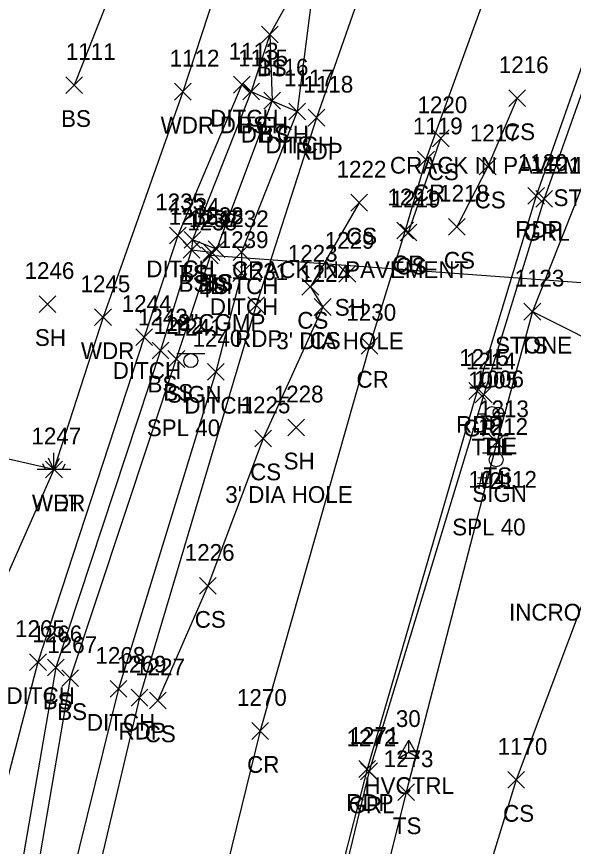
# Model space of a CAD drawing. Extents: x 1551995 to 1555700, y 777276 to 783130.
# Drawn here: x 1554895.2 to 1554961.7, y 778019 to 778118.1 of the extents above; entities that cross this region are included whole.
import ezdxf

# ---------------------------------------------------------------- set-up
doc = ezdxf.new("R2010")
doc.units = 0
for name, color, linetype in [('C_A', 7, 'Continuous'), ('C_C', 7, 'Continuous'), ('C_I', 7, 'Continuous'), ('CBP', 7, 'Continuous'), ('CPSM', 7, 'Continuous'), ('D_A', 7, 'Continuous'), ('D_C', 7, 'Continuous'), ('D_I', 7, 'Continuous'), ('D_TIC', 7, 'Continuous'), ('DCP', 7, 'Continuous'), ('DD', 7, 'Continuous'), ('L_A', 7, 'Continuous'), ('L_C', 7, 'Continuous'), ('L_I', 7, 'Continuous'), ('L_TIC', 7, 'Continuous'), ('LASF', 7, 'Continuous'), ('LAWA', 7, 'Continuous'), ('LELB', 7, 'Continuous'), ('LWET', 7, 'Continuous'), ('P_A', 7, 'Continuous'), ('P_I', 7, 'Continuous'), ('P_TIC', 7, 'Continuous'), ('PET', 7, 'Continuous'), ('PRC', 7, 'Continuous'), ('R_A', 7, 'Continuous'), ('R_I', 7, 'Continuous'), ('R_TIC', 7, 'Continuous'), ('RGR', 7, 'Continuous'), ('S_A', 7, 'Continuous'), ('S_C', 7, 'Continuous'), ('S_I', 7, 'Continuous'), ('SSGN', 7, 'Continuous'), ('U_A', 7, 'Continuous'), ('U_C', 7, 'Continuous'), ('U_I', 7, 'Continuous'), ('UP', 7, 'Continuous')]:
    doc.layers.add(name, color=color, linetype=linetype)

msp = doc.modelspace()

# ---------------------------------------------------------------- linework, layer by layer
at = {"layer": 'CBP'}
for radius in [0.625, 0.0833]:
    msp.add_circle((1554952.736, 778070.817), radius, dxfattribs=at)
at = {"layer": 'CPSM'}
for p, q in [((1554940.771, 778029.523), (1554942.021, 778031.688)), ((1554943.271, 778029.523), (1554942.021, 778031.688)), ((1554942.022, 778030.244), (1554942.021, 778031.688)), ((1554940.771, 778029.523), (1554942.022, 778030.244)), ((1554942.022, 778030.244), (1554942.022, 778030.244)), ((1554942.022, 778030.244), (1554943.271, 778029.523)), ((1554940.771, 778029.523), (1554943.271, 778029.523))]:
    msp.add_line(p, q, dxfattribs=at)
at = {"layer": 'D_TIC'}
for points in [[(1554921.059, 778108.964), (1554923.059, 778110.964)], [(1554923.059, 778108.964), (1554921.059, 778110.964)], [(1554921.059, 778108.964), (1554923.059, 778110.964)], [(1554923.059, 778108.964), (1554921.059, 778110.964)], [(1554922.185, 778108.151), (1554924.185, 778110.151)], [(1554924.185, 778108.151), (1554922.185, 778110.151)], [(1554924.692, 778107.048), (1554926.692, 778109.048)], [(1554926.692, 778107.048), (1554924.692, 778109.048)], [(1554927.668, 778105.766), (1554929.668, 778107.766)], [(1554929.668, 778105.766), (1554927.668, 778107.766)], [(1554913.415, 778090.958), (1554915.415, 778092.958)], [(1554915.415, 778090.958), (1554913.415, 778092.958)], [(1554917.237, 778088.557), (1554919.237, 778090.557)], [(1554919.237, 778088.557), (1554917.237, 778090.557)], [(1554921.027, 778088.942), (1554923.027, 778090.942)], [(1554923.027, 778088.942), (1554921.027, 778090.942)], [(1554921.01, 778086.442), (1554923.01, 778088.442)], [(1554923.01, 778086.442), (1554921.01, 778088.442)], [(1554909.403, 778078.818), (1554911.403, 778080.818)], [(1554911.403, 778078.818), (1554909.403, 778080.818)], [(1554917.959, 778074.67), (1554919.959, 778076.67)], [(1554919.959, 778074.67), (1554917.959, 778076.67)], [(1554896.71, 778039.992), (1554898.71, 778041.992)], [(1554898.71, 778039.992), (1554896.71, 778041.992)], [(1554906.316, 778036.793), (1554908.316, 778038.793)], [(1554908.316, 778036.793), (1554906.316, 778038.793)]]:
    msp.add_lwpolyline(points, dxfattribs=at)
at = {"layer": 'DCP'}
msp.add_lwpolyline([(1554979.381, 778085.04), (1554918.237, 778089.557)], dxfattribs=at)
at = {"layer": 'DD'}
for points in [[(1554922.059, 778109.964), (1554923.185, 778109.151), (1554925.692, 778108.048), (1554928.668, 778106.766), (1554922.027, 778089.942), (1554922.01, 778087.442), (1554918.959, 778075.67), (1554907.316, 778037.793), (1554897.01, 777996.113), (1554888.713, 777961.747), (1554879.522, 777917.823), (1554870.918, 777875.826), (1554859.526, 777827.027), (1554848.282, 777775.295), (1554842.422, 777742.654), (1554832.082, 777696.159), (1554826.684, 777674.459), (1554825.9, 777662.939)], [(1554922.059, 778109.964), (1554914.415, 778091.958), (1554910.403, 778079.818), (1554897.71, 778040.992), (1554886.569, 777998.503), (1554878.331, 777965.3), (1554870.216, 777919.722), (1554862.183, 777878.393), (1554853.394, 777826.983), (1554841.815, 777777.5)]]:
    msp.add_lwpolyline(points, dxfattribs=at)
at = {"layer": 'L_TIC'}
for points in [[(1554924.414, 778114.961), (1554926.414, 778116.961)], [(1554926.414, 778114.961), (1554924.414, 778116.961)], [(1554924.414, 778114.961), (1554926.414, 778116.961)], [(1554926.414, 778114.961), (1554924.414, 778116.961)], [(1554901.026, 778108.912), (1554903.026, 778110.912)], [(1554903.026, 778108.912), (1554901.026, 778110.912)], [(1554914.004, 778108.124), (1554916.004, 778110.124)], [(1554916.004, 778108.124), (1554914.004, 778110.124)], [(1554922.185, 778108.151), (1554924.185, 778110.151)], [(1554924.185, 778108.151), (1554922.185, 778110.151)], [(1554953.956, 778107.336), (1554955.956, 778109.336)], [(1554955.956, 778107.336), (1554953.956, 778109.336)], [(1554924.692, 778107.048), (1554926.692, 778109.048)], [(1554926.692, 778107.048), (1554924.692, 778109.048)], [(1554927.668, 778105.766), (1554929.668, 778107.766)], [(1554929.668, 778105.766), (1554927.668, 778107.766)], [(1554944.839, 778102.555), (1554946.839, 778104.555)], [(1554946.839, 778102.555), (1554944.839, 778104.555)], [(1554950.445, 778099.189), (1554952.445, 778101.189)], [(1554952.445, 778099.189), (1554950.445, 778101.189)], [(1554935.083, 778094.864), (1554937.083, 778096.864)], [(1554937.083, 778094.864), (1554935.083, 778096.864)], [(1554940.982, 778091.293), (1554942.982, 778093.293)], [(1554942.982, 778091.293), (1554940.982, 778093.293)], [(1554946.77, 778091.99), (1554948.77, 778093.99)], [(1554948.77, 778091.99), (1554946.77, 778093.99)], [(1554915.16, 778090.424), (1554917.16, 778092.424)], [(1554917.16, 778090.424), (1554915.16, 778092.424)], [(1554915.16, 778090.424), (1554917.16, 778092.424)], [(1554917.16, 778090.424), (1554915.16, 778092.424)], [(1554918.027, 778089.313), (1554920.027, 778091.313)], [(1554920.027, 778089.313), (1554918.027, 778091.313)], [(1554918.027, 778089.313), (1554920.027, 778091.313)], [(1554920.027, 778089.313), (1554918.027, 778091.313)], [(1554915.061, 778089.22), (1554917.061, 778091.22)], [(1554917.061, 778089.22), (1554915.061, 778091.22)], [(1554915.061, 778089.22), (1554917.061, 778091.22)], [(1554917.061, 778089.22), (1554915.061, 778091.22)], [(1554917.436, 778088.95), (1554919.436, 778090.95)], [(1554919.436, 778088.95), (1554917.436, 778090.95)], [(1554917.436, 778088.95), (1554919.436, 778090.95)], [(1554919.436, 778088.95), (1554917.436, 778090.95)], [(1554933.677, 778086.362), (1554935.677, 778088.362)], [(1554935.677, 778086.362), (1554933.677, 778088.362)], [(1554929.254, 778084.816), (1554931.254, 778086.816)], [(1554931.254, 778084.816), (1554929.254, 778086.816)], [(1554897.853, 778082.755), (1554899.853, 778084.755)], [(1554899.853, 778082.755), (1554897.853, 778084.755)], [(1554930.729, 778082.402), (1554932.729, 778084.402)], [(1554932.729, 778082.402), (1554930.729, 778084.402)], [(1554955.784, 778081.852), (1554957.784, 778083.852)], [(1554957.784, 778081.852), (1554955.784, 778083.852)], [(1554955.784, 778081.852), (1554957.784, 778083.852)], [(1554957.784, 778081.852), (1554955.784, 778083.852)], [(1554904.48, 778081.177), (1554906.48, 778083.177)], [(1554906.48, 778081.177), (1554904.48, 778083.177)], [(1554911.352, 778077.199), (1554913.352, 778079.199)], [(1554913.352, 778077.199), (1554911.352, 778079.199)], [(1554913.238, 778076.199), (1554915.238, 778078.199)], [(1554915.238, 778076.199), (1554913.238, 778078.199)], [(1554927.574, 778068.009), (1554929.574, 778070.009)], [(1554929.574, 778068.009), (1554927.574, 778070.009)], [(1554923.613, 778066.708), (1554925.613, 778068.708)], [(1554925.613, 778066.708), (1554923.613, 778068.708)], [(1554951.543, 778066.248), (1554953.543, 778068.248)], [(1554953.543, 778066.248), (1554951.543, 778068.248)], [(1554898.619, 778063.005), (1554900.619, 778065.005)], [(1554900.619, 778063.005), (1554898.619, 778065.005)], [(1554916.995, 778049.092), (1554918.995, 778051.092)], [(1554918.995, 778049.092), (1554916.995, 778051.092)], [(1554898.833, 778039.361), (1554900.833, 778041.361)], [(1554900.833, 778039.361), (1554898.833, 778041.361)], [(1554900.567, 778038.074), (1554902.567, 778040.074)], [(1554902.567, 778038.074), (1554900.567, 778040.074)], [(1554911.02, 778035.423), (1554913.02, 778037.423)], [(1554913.02, 778035.423), (1554911.02, 778037.423)], [(1554953.842, 778025.927), (1554955.842, 778027.927)], [(1554955.842, 778025.927), (1554953.842, 778027.927)], [(1554953.842, 778025.927), (1554955.842, 778027.927)], [(1554955.842, 778025.927), (1554953.842, 778027.927)], [(1554940.704, 778024.446), (1554942.704, 778026.446)], [(1554942.704, 778024.446), (1554940.704, 778026.446)]]:
    msp.add_lwpolyline(points, dxfattribs=at)
at = {"layer": 'LASF'}
msp.add_lwpolyline([(1554963.77, 778100.46), (1554956.784, 778082.852), (1554967.526, 778077.48), (1554970.987, 778074.929), (1554972.457, 778074.451), (1554981.296, 778074.525)], dxfattribs=at)
at = {"layer": 'LAWA'}
msp.add_lwpolyline([(1555000.959, 778294.871), (1554977.329, 778249.83), (1554953.65, 778203.431), (1554934.128, 778158.372), (1554921.739, 778129.694), (1554915.004, 778109.124), (1554905.48, 778082.177), (1554899.619, 778064.005), (1554889.875, 778042.086), (1554882.71, 778000.014), (1554871.693, 777971.466), (1554868.372, 777961.536), (1554861.965, 777920.449), (1554858.528, 777878.75), (1554855.375, 777850.348), (1554848.666, 777827.396), (1554836.715, 777779.634)], dxfattribs=at)
at = {"layer": 'LELB'}
for points in [[(1554991.435, 778299.233), (1554965.179, 778257.458), (1554942.555, 778207.52), (1554927.413, 778168.062), (1554913.271, 778138.258), (1554902.026, 778109.912)], [(1555012.411, 778287.512), (1554987.423, 778242.351), (1554964.945, 778198.341), (1554949.463, 778165.728), (1554942.042, 778145.432), (1554936.477, 778135.997), (1554931.202, 778126.363), (1554925.414, 778115.961), (1554925.692, 778108.048), (1554919.027, 778090.313), (1554918.436, 778089.95), (1554914.238, 778077.199), (1554901.567, 778039.074), (1554894.389, 777997.124), (1554883.879, 777962.737), (1554876.081, 777918.207), (1554866.798, 777876.468), (1554857.763, 777827.38), (1554846.358, 777775.83)], [(1554943.026, 778145), (1554938.515, 778134.685), (1554931.202, 778126.363), (1554928.668, 778106.766)], [(1554925.414, 778115.961), (1554923.185, 778109.151), (1554916.16, 778091.424), (1554916.061, 778090.22), (1554912.352, 778078.199), (1554899.833, 778040.361), (1554892.758, 777999.543), (1554881.047, 777964.265), (1554872.657, 777919.49), (1554864.333, 777877.23), (1554855.731, 777827.332), (1554843.831, 777776.523)], [(1554954.956, 778108.336), (1554951.445, 778100.189), (1554947.77, 778092.99)], [(1554941.982, 778092.293), (1554945.839, 778103.555)], [(1554936.083, 778095.864), (1554930.254, 778085.816), (1554931.729, 778083.402), (1554924.613, 778067.708), (1554917.995, 778050.092), (1554912.02, 778036.423)], [(1554919.027, 778090.313), (1554916.16, 778091.424)], [(1554916.061, 778090.22), (1554918.436, 778089.95)], [(1554956.784, 778082.852), (1554952.543, 778067.248), (1554941.704, 778025.446), (1554932.228, 777987.421), (1554924.92, 777953.424), (1554914.283, 777909.637), (1554906.044, 777867.543), (1554895.88, 777821.336), (1554882.234, 777767.046), (1554874.85, 777730.372), (1554865.159, 777689.058), (1554854.058, 777643.962), (1554841.072, 777598.558), (1554825.798, 777560.577)], [(1554967.222, 778059.881), (1554954.842, 778026.927)], [(1554954.842, 778026.927), (1554940.94, 777981.637), (1554932.866, 777954.143), (1554929.76, 777924.842), (1554918.746, 777893.914), (1554912.386, 777848.48), (1554900.257, 777799.704), (1554891.709, 777757.623), (1554881.433, 777720.269), (1554874.575, 777680.059), (1554873.826, 777672.653), (1554864.116, 777644.243), (1554854.563, 777607.139), (1554832.257, 777556.579)]]:
    msp.add_lwpolyline(points, dxfattribs=at)
at = {"layer": 'LWET'}
for p, q in [((1554899.619, 778064.005), (1554899.619, 778066.005)), ((1554898.619, 778064.005), (1554898.286, 778064.672)), ((1554899.619, 778064.005), (1554898.952, 778065.339)), ((1554899.619, 778064.005), (1554900.286, 778065.339)), ((1554900.619, 778064.005), (1554900.952, 778064.672)), ((1554901.619, 778064.005), (1554897.619, 778064.005))]:
    msp.add_line(p, q, dxfattribs=at)
msp.add_lwpolyline([(1554899.619, 778064.005), (1554891.872, 778065.739), (1554875.598, 778057.423), (1554858.793, 778055.838), (1554846.247, 778065.446), (1554838.512, 778079.969), (1554828.477, 778068.893), (1554835.848, 778063.304), (1554853.838, 778050.339), (1554871.644, 778048.288), (1554884.34, 778050.676), (1554889.875, 778042.086)], dxfattribs=at)
at = {"layer": 'P_TIC'}
for points in [[(1554929.99, 778105.015), (1554931.99, 778107.015)], [(1554931.99, 778105.015), (1554929.99, 778107.015)], [(1554943.074, 778100.03), (1554945.074, 778102.03)], [(1554945.074, 778100.03), (1554943.074, 778102.03)], [(1554956.252, 778095.668), (1554958.252, 778097.668)], [(1554958.252, 778095.668), (1554956.252, 778097.668)], [(1554940.59, 778091.542), (1554942.59, 778093.542)], [(1554942.59, 778091.542), (1554940.59, 778093.542)], [(1554922.775, 778082.627), (1554924.775, 778084.627)], [(1554924.775, 778082.627), (1554922.775, 778084.627)], [(1554936.337, 778077.768), (1554938.337, 778079.768)], [(1554938.337, 778077.768), (1554936.337, 778079.768)], [(1554949.174, 778072.377), (1554951.174, 778074.377)], [(1554951.174, 778072.377), (1554949.174, 778074.377)], [(1554908.847, 778035.75), (1554910.847, 778037.75)], [(1554910.847, 778035.75), (1554908.847, 778037.75)], [(1554923.265, 778031.769), (1554925.265, 778033.769)], [(1554925.265, 778031.769), (1554923.265, 778033.769)], [(1554936.056, 778027.225), (1554938.056, 778029.225)], [(1554938.056, 778027.225), (1554936.056, 778029.225)]]:
    msp.add_lwpolyline(points, dxfattribs=at)
at = {"layer": 'PET'}
for points in [[(1555086.851, 778385.987), (1555058.531, 778347.951), (1555034.128, 778312.764), (1555016.687, 778284.76), (1554990.685, 778240.379), (1554968.052, 778196.327), (1554953.028, 778164.249), (1554940.373, 778132.83), (1554930.99, 778106.015), (1554923.775, 778083.627), (1554909.847, 778036.75), (1554900.041, 777995.37), (1554891.675, 777961.455), (1554881.898, 777917.033), (1554872.924, 777875.283), (1554862.745, 777826.663), (1554851.188, 777774.321)], [(1555108.516, 778369.807), (1555078.861, 778330.232), (1555056.918, 778298.279), (1555038.326, 778268.724), (1555013, 778223.52), (1554996.002, 778190.398), (1554978.907, 778154.53), (1554967.237, 778125.108), (1554957.252, 778096.668), (1554950.174, 778073.377), (1554937.056, 778028.225), (1554926.799, 777988.52), (1554918.725, 777954.593), (1554908.462, 777910.078), (1554899.75, 777869.143), (1554889.897, 777822.391), (1554877.403, 777767.736)]]:
    msp.add_lwpolyline(points, dxfattribs=at)
at = {"layer": 'PRC'}
msp.add_lwpolyline([(1555098.332, 778377.476), (1555069.71, 778339.493), (1555045.494, 778304.701), (1555028.734, 778278.055), (1555002.892, 778234.082), (1554979.995, 778189.5), (1554966.223, 778159.175), (1554954.385, 778129.465), (1554944.074, 778101.03), (1554941.59, 778092.542), (1554937.337, 778078.768), (1554924.265, 778032.769), (1554914.158, 777991.616), (1554905.843, 777957.856), (1554895.982, 777913.961), (1554886.876, 777872.587), (1554876.719, 777824.263), (1554864.603, 777770.35)], dxfattribs=at)
at = {"layer": 'R_TIC'}
for points in [[(1554957.203, 778095.319), (1554959.203, 778097.319)], [(1554959.203, 778095.319), (1554957.203, 778097.319)], [(1554949.966, 778071.943), (1554951.966, 778073.943)], [(1554951.966, 778071.943), (1554949.966, 778073.943)], [(1554936.267, 778026.949), (1554938.267, 778028.949)], [(1554938.267, 778026.949), (1554936.267, 778028.949)]]:
    msp.add_lwpolyline(points, dxfattribs=at)
at = {"layer": 'RGR'}
msp.add_lwpolyline([(1555039.562, 778268.303), (1555013.623, 778223), (1554996.626, 778189.883), (1554979.879, 778154.083), (1554968.244, 778124.645), (1554958.203, 778096.319), (1554950.966, 778072.943), (1554937.267, 778027.949), (1554927.647, 777988.098), (1554919.661, 777954.368), (1554909.72, 777910.106), (1554900.5, 777868.177), (1554890.694, 777822.536), (1554878.363, 777767.589), (1554870.519, 777731.321), (1554860.897, 777689.381), (1554849.553, 777645.137), (1554835.811, 777600.33), (1554822.786, 777564.146), (1554817.066, 777548.719), (1554816.698, 777536.059)], dxfattribs=at)
at = {"layer": 'SSGN'}
for p, q in [((1554914.318, 778077.834), (1554917.651, 778077.834)), ((1554915.965, 778077.001), (1554915.965, 778077.001)), ((1554950.818, 778065.982), (1554954.151, 778065.982)), ((1554952.465, 778065.149), (1554952.465, 778065.149))]:
    msp.add_line(p, q, dxfattribs=at)
for centre in [(1554915.965, 778077.001), (1554952.465, 778065.149)]:
    msp.add_circle(centre, 0.833, dxfattribs=at)
at = {"layer": 'UP'}
for p, q in [((1554950.298, 778070.666), (1554951.124, 778070.666)), ((1554951.958, 778070.671), (1554951.958, 778070.671)), ((1554953.624, 778070.671), (1554952.791, 778070.671)), ((1554952.791, 778070.671), (1554952.791, 778070.671)), ((1554953.624, 778070.671), (1554953.624, 778070.671))]:
    msp.add_line(p, q, dxfattribs=at)
msp.add_circle((1554951.958, 778070.671), 0.833, dxfattribs=at)

# ---------------------------------------------------------------- texts
at = {"layer": 'C_A'}
for s, p in [('TIE', (1554950.815, 778065.817)), ('HVCTRL', (1554936.715, 778025.244))]:
    msp.add_text(s, height=2, dxfattribs=at).set_placement(p)
at = {"layer": 'C_C'}
msp.add_text('104.12', height=2, dxfattribs=at).set_placement((1554949.146, 778061.817))
at = {"layer": 'C_I'}
for s, p in [('1006', (1554949.831, 778073.817)), ('30', (1554940.471, 778033.244))]:
    msp.add_text(s, height=2, dxfattribs=at).set_placement(p)
at = {"layer": 'D_A'}
for s, p in [('DITCH', (1554918.295, 778104.964)), ('DITCH', (1554918.295, 778104.964)), ('DITCH', (1554919.421, 778104.151)), ('DITCH', (1554921.929, 778103.048)), ('DITCH', (1554924.904, 778101.766)), ('DITCH', (1554910.651, 778086.958)), ('P', (1554917.615, 778084.557)), ('DITCH', (1554918.264, 778084.942)), ('DITCH', (1554918.246, 778082.442)), ('DITCH', (1554906.639, 778074.818)), ('DITCH', (1554915.195, 778070.67)), ('DITCH', (1554893.946, 778035.992)), ('DITCH', (1554903.552, 778032.793))]:
    msp.add_text(s, height=2, dxfattribs=at).set_placement(p)
at = {"layer": 'D_C'}
msp.add_text('18"CGMP', height=2, dxfattribs=at).set_placement((1554912.938, 778080.557))
at = {"layer": 'D_I'}
for s, p in [('1113', (1554920.5, 778112.964)), ('1113', (1554920.5, 778112.964)), ('1115', (1554921.626, 778112.151)), ('1116', (1554924.078, 778111.048)), ('1117', (1554927.109, 778109.766)), ('1235', (1554911.722, 778094.958)), ('1238', (1554915.544, 778092.557)), ('1232', (1554919.335, 778092.942)), ('1239', (1554919.309, 778090.442)), ('1244', (1554907.71, 778082.818)), ('1240', (1554916.179, 778078.67)), ('1265', (1554894.97, 778043.992)), ('1268', (1554904.576, 778040.793))]:
    msp.add_text(s, height=2, dxfattribs=at).set_placement(p)
at = {"layer": 'L_A'}
for s, p in [('BS', (1554923.855, 778110.961)), ('BS', (1554923.855, 778110.961)), ('BS', (1554900.467, 778104.912)), ('BS', (1554921.626, 778104.151)), ('WDR', (1554912.366, 778104.124)), ('CS', (1554953.397, 778103.336)), ('BS', (1554924.133, 778103.048)), ('TS', (1554927.077, 778101.766)), ('CS', (1554944.28, 778098.555)), ('STONE', (1554959.313, 778095.46)), ('STONE', (1554959.313, 778095.46)), ('CS', (1554949.886, 778095.189)), ('CS', (1554934.524, 778090.864)), ('CS', (1554940.422, 778087.293)), ('CS', (1554946.211, 778087.99)), ('TS', (1554914.569, 778086.424)), ('BS', (1554914.601, 778086.424)), ('TS', (1554917.436, 778085.313)), ('BS', (1554917.468, 778085.313)), ('BS', (1554914.502, 778085.22)), ('BS', (1554914.502, 778085.22)), ('BS', (1554916.877, 778084.95)), ('BS', (1554916.877, 778084.95)), ('SH', (1554933.165, 778082.362)), ('CS', (1554928.695, 778080.816)), ('SH', (1554897.341, 778078.755)), ('CS', (1554930.17, 778078.402)), ('STONE', (1554952.327, 778077.852)), ('TS', (1554955.193, 778077.852)), ('WDR', (1554902.842, 778077.177)), ('BS', (1554910.793, 778073.199)), ('BS', (1554912.679, 778072.199)), ('SH', (1554927.062, 778064.009)), ('CS', (1554923.054, 778062.708)), ('TS', (1554950.952, 778062.248)), ('WDR', (1554896.981, 778059.005)), ('WET', (1554896.997, 778059.005)), ('CS', (1554916.436, 778045.092)), ('BS', (1554898.274, 778035.361)), ('BS', (1554900.008, 778034.074)), ('CS', (1554910.461, 778031.423)), ('CS', (1554953.283, 778021.927)), ('CS', (1554953.283, 778021.927)), ('TS', (1554940.114, 778020.446))]:
    msp.add_text(s, height=2, dxfattribs=at).set_placement(p)
at = {"layer": 'L_C'}
for s, p in [('CRACK IN PAVEMENT', (1554939.768, 778099.336)), ('CRACK IN PAVEMENT', (1554920.894, 778086.864)), ("3' DIA HOLE", (1554926.189, 778078.362)), ("3' DIA HOLE", (1554920.086, 778060.009))]:
    msp.add_text(s, height=2, dxfattribs=at).set_placement(p)
at = {"layer": 'L_I'}
for s, p in [('1111', (1554901.034, 778112.912)), ('1112', (1554913.445, 778112.124)), ('1115', (1554921.626, 778112.151)), ('1216', (1554952.775, 778111.336)), ('1116', (1554924.078, 778111.048)), ('1117', (1554927.109, 778109.766)), ('1220', (1554943.059, 778106.555)), ('1217', (1554949.319, 778103.189)), ('1222', (1554933.39, 778098.864)), ('1219', (1554939.848, 778095.293)), ('1218', (1554945.644, 778095.99)), ('1234', (1554913.467, 778094.424)), ('1234', (1554913.467, 778094.424)), ('1233', (1554916.334, 778093.313)), ('1233', (1554916.334, 778093.313)), ('1236', (1554913.313, 778093.22)), ('1236', (1554913.313, 778093.22)), ('1237', (1554915.743, 778092.95)), ('1237', (1554915.743, 778092.95)), ('1229', (1554931.977, 778090.362)), ('1223', (1554927.561, 778088.816)), ('1246', (1554896.105, 778086.755)), ('1224', (1554929.036, 778086.402)), ('1123', (1554954.658, 778085.852)), ('1123', (1554954.658, 778085.852)), ('1245', (1554902.787, 778085.177)), ('1243', (1554909.66, 778081.199)), ('1242', (1554911.545, 778080.199)), ('1228', (1554925.881, 778072.009)), ('1225', (1554921.92, 778070.708)), ('1213', (1554950.417, 778070.248)), ('1247', (1554896.926, 778067.005)), ('1247', (1554896.926, 778067.005)), ('1226', (1554915.247, 778053.092)), ('1266', (1554897.037, 778043.361)), ('1267', (1554898.827, 778042.074)), ('1227', (1554909.327, 778039.423)), ('1170', (1554952.629, 778029.927)), ('1170', (1554952.629, 778029.927)), ('1273', (1554939.011, 778028.446))]:
    msp.add_text(s, height=2, dxfattribs=at).set_placement(p)
at = {"layer": 'P_A'}
for s, p in [('RDP', (1554928.478, 778101.015)), ('CR', (1554942.507, 778096.03)), ('RDP', (1554954.74, 778091.668)), ('CR', (1554940.023, 778087.542)), ('RDP', (1554921.263, 778078.627)), ('CR', (1554935.77, 778073.768)), ('RDP', (1554947.663, 778068.377)), ('RDP', (1554907.336, 778031.75)), ('CR', (1554922.698, 778027.769)), ('RDP', (1554934.544, 778023.225))]:
    msp.add_text(s, height=2, dxfattribs=at).set_placement(p)
at = {"layer": 'P_I'}
for s, p in [('1118', (1554929.431, 778109.015)), ('1119', (1554942.507, 778104.03)), ('1120', (1554955.039, 778099.668)), ('1221', (1554939.464, 778095.542)), ('1231', (1554921.649, 778086.627)), ('1230', (1554934.558, 778081.768)), ('1215', (1554948.048, 778076.377)), ('1269', (1554907.099, 778039.75)), ('1270', (1554921.486, 778035.769)), ('1271', (1554934.93, 778031.225))]:
    msp.add_text(s, height=2, dxfattribs=at).set_placement(p)
at = {"layer": 'R_A'}
for p in [(1554955.746, 778091.319), (1554948.509, 778067.943), (1554934.81, 778022.949)]:
    msp.add_text('GRL', height=2, dxfattribs=at).set_placement(p)
at = {"layer": 'R_I'}
for s, p in [('1121', (1554956.644, 778099.319)), ('1214', (1554948.84, 778075.943)), ('1272', (1554934.574, 778030.949))]:
    msp.add_text(s, height=2, dxfattribs=at).set_placement(p)
at = {"layer": 'S_A'}
for p in [(1554913.103, 778071.981), (1554949.603, 778060.128)]:
    msp.add_text('SIGN', height=2, dxfattribs=at).set_placement(p)
at = {"layer": 'S_C'}
for p in [(1554910.709, 778067.981), (1554947.209, 778056.128)]:
    msp.add_text('SPL 40', height=2, dxfattribs=at).set_placement(p)
at = {"layer": 'S_I'}
for s, p in [('1241', (1554913.819, 778079.981)), ('1212', (1554950.319, 778068.128))]:
    msp.add_text(s, height=2, dxfattribs=at).set_placement(p)
at = {"layer": 'U_A'}
msp.add_text('TEL', height=2, dxfattribs=at).set_placement((1554949.517, 778065.671))
at = {"layer": 'U_C'}
for s, p in [('#21', (1554950.162, 778061.671)), ('INCRONOMETER #1', (1554953.995, 778045.955))]:
    msp.add_text(s, height=2, dxfattribs=at).set_placement(p)
at = {"layer": 'U_I'}
msp.add_text('1005', height=2, dxfattribs=at).set_placement((1554949.107, 778073.671))

doc.saveas('drawing.dxf')
